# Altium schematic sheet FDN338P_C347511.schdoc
size 127 x 101 mm
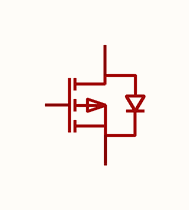
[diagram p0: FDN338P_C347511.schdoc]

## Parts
Q?  fdn338p(umw)  [SOT-23-3_L2.9-W1.3-P1.90-LS2.4-BR]  (value not drawn)

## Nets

Not connected (* = marked no-connect by the designer): Q? 1(G) 2(S) 3(D)

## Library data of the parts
Q? = fdn338p(umw): 数量:1个P沟道;漏源电压(Vdss):20V;连续漏极电流(Id):2.8A;导通电阻(RDS(on)):90mΩ@4.5V；110mΩ@2.5V;耗散功率(Pd):400mW;阈值电压(Vgs(th)):1V;; Manufacturer: UMW(友台半导体); Symbol: FDN338P_C347511; AddInBom: yes; ModelId: c62791f0466c4ae2a892c056b845b0ca; ModelName: SOT-23-3P_L2.9-W1.3-H1.0-LS2.4-P0.95; ModelTransform: 98.425,114.173,0,180,0,0,0.0005,-0.0005,0; Number: 1个P沟道; Drain to Source Voltage: 20V; Current - Continuous Drain(Id): 2.8A; Pd - Power Dissipation: 400mW; Gate Threshold Voltage (Vgs(th)): 1V; Gate Charge(Qg): 5.5nC@2.5V; Input Capacitance(Ciss): 405pF; Reverse Transfer Capacitance (Crss@Vds): 55pF; Type: P沟道; Output Capacitance(Coss): 75pF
